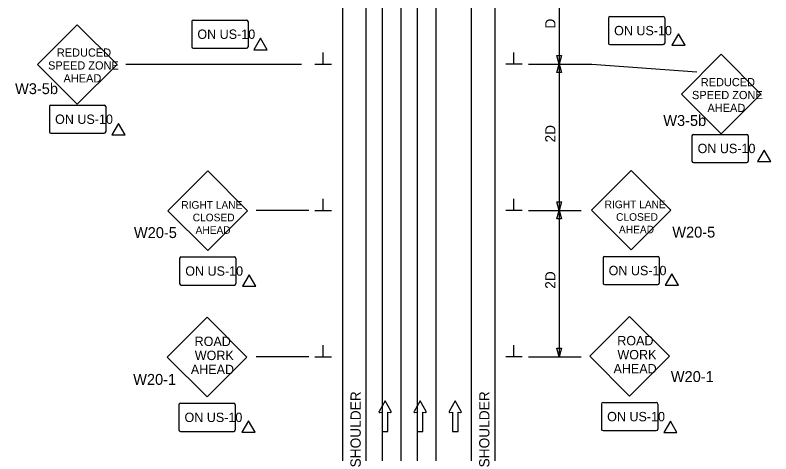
# Model space of a CAD drawing. Extents: x 16303 to 18475, y 5704 to 6974.
# Drawn here: x 16730 to 17246, y 6153 to 6453 of the extents above; entities that cross this region are included whole.
import ezdxf

# ---------------------------------------------------------------- set-up
doc = ezdxf.new("R2010")
doc.units = 0
for name, color, linetype in [('ALI_LEGAL_EX', 7, 'Continuous'), ('MT_SCRATCH_LEVEL_E', 7, 'Continuous'), ('PAVT_EDGE_EX', 7, 'Continuous'), ('TRAFFIC_SIGNS_PR', 7, 'Continuous'), ('TYPICAL_TEXT_DIMEN_PR', 7, 'Continuous')]:
    doc.layers.add(name, color=color, linetype=linetype)

msp = doc.modelspace()

# ---------------------------------------------------------------- linework, layer by layer
at = {"layer": 'ALI_LEGAL_EX'}
for p, q in [((16980.68, 6974.12), (16980.68, 6155.98)), ((17004.68, 6974.12), (17004.68, 6155.98)), ((16980.68, 6877.04), (16980.68, 6013.12)), ((17004.68, 6877.04), (17004.68, 6013.12)), ((16993.65, 6024.8), (16993.65, 6525.15)), ((17017.65, 6024.8), (17017.65, 6525.15))]:
    msp.add_line(p, q, dxfattribs=at)
for points in [[(16993.65, 6424.8), (16993.65, 6449.8)], [(17017.65, 6424.8), (17017.65, 6449.8)], [(16993.65, 6324.8), (16993.65, 6349.8)], [(17017.65, 6324.8), (17017.65, 6349.8)], [(16993.65, 6224.8), (16993.65, 6249.8)], [(17017.65, 6224.8), (17017.65, 6249.8)]]:
    msp.add_lwpolyline(points, dxfattribs=at)
at = {"layer": 'MT_SCRATCH_LEVEL_E'}
for p, q in [((16982.72, 6189.09), (16978.61, 6181.85)), ((16986.86, 6181.85), (16982.72, 6189.09)), ((17006.62, 6189.09), (17002.51, 6181.85)), ((17010.77, 6181.85), (17006.62, 6189.09)), ((17030.67, 6189.09), (17026.56, 6181.85)), ((17034.82, 6181.85), (17030.67, 6189.09)), ((16979.09, 6181.17), (16980.87, 6181.49)), ((16980.87, 6181.49), (16980.87, 6168.23)), ((16984.61, 6168.23), (16984.61, 6181.49)), ((16984.61, 6181.49), (16986.38, 6181.17)), ((17002.99, 6181.17), (17004.77, 6181.49)), ((17004.77, 6181.49), (17004.77, 6168.23)), ((17008.51, 6168.23), (17008.51, 6181.49)), ((17008.51, 6181.49), (17010.29, 6181.17)), ((17027.05, 6181.17), (17028.82, 6181.49)), ((17028.82, 6181.49), (17028.82, 6168.23)), ((17032.56, 6168.23), (17032.56, 6181.49)), ((17032.56, 6181.49), (17034.34, 6181.17)), ((16980.87, 6168.23), (16984.61, 6168.23)), ((17004.77, 6168.23), (17008.51, 6168.23)), ((17028.82, 6168.23), (17032.56, 6168.23))]:
    msp.add_line(p, q, dxfattribs=at)
for centre, start, end in [((16979.01, 6181.63), 150.4248, 279.9638), ((16986.45, 6181.63), 260.0362, 29.7731), ((17002.92, 6181.63), 150.4248, 279.9638), ((17010.36, 6181.63), 260.0362, 29.7731), ((17026.97, 6181.63), 150.4248, 279.9638), ((17034.41, 6181.63), 260.0362, 29.7731)]:
    msp.add_arc(centre, 0.463, start, end, dxfattribs=at)
at = {"layer": 'PAVT_EDGE_EX'}
for p, q in [((16953.65, 6525.15), (16953.65, 6062.71)), ((16969.65, 6525.15), (16969.65, 6062.71)), ((17041.65, 6525.15), (17041.65, 6062.71)), ((17057.65, 6525.15), (17057.65, 6062.71))]:
    msp.add_line(p, q, dxfattribs=at)
at = {"layer": 'TRAFFIC_SIGNS_PR'}
for p, q in [((17135.31, 6450.77), (17135.31, 6433.57)), ((17136.31, 6451.77), (17172.71, 6451.77)), ((17173.71, 6450.77), (17173.71, 6433.57)), ((16772.61, 6446.21), (16745.46, 6419.05)), ((16799.76, 6419.05), (16772.61, 6446.21)), ((16850.76, 6448.3), (16850.76, 6431.1)), ((16851.76, 6449.3), (16888.17, 6449.3)), ((16889.17, 6448.3), (16889.17, 6431.1)), ((16851.76, 6430.1), (16888.17, 6430.1)), ((17136.31, 6432.57), (17172.71, 6432.57)), ((17212.26, 6425.99), (17185.11, 6398.83)), ((17239.41, 6398.83), (17212.26, 6425.99)), ((16745.46, 6419.05), (16772.61, 6391.9)), ((16772.61, 6391.9), (16799.76, 6419.05)), ((17185.11, 6398.83), (17212.26, 6371.68)), ((17212.26, 6371.68), (17239.41, 6398.83)), ((16753.62, 6390.21), (16753.62, 6373.01)), ((16754.62, 6391.21), (16791.02, 6391.21)), ((16792.02, 6390.21), (16792.02, 6373.01)), ((16754.62, 6372.01), (16791.02, 6372.01)), ((17192.3, 6370.22), (17192.3, 6353.02)), ((17193.3, 6371.22), (17229.7, 6371.22)), ((17230.7, 6370.22), (17230.7, 6353.02)), ((17193.3, 6352.02), (17229.7, 6352.02)), ((16861.7, 6346.22), (16834.54, 6319.06)), ((16888.86, 6319.06), (16861.7, 6346.22)), ((17150.76, 6346.55), (17123.6, 6319.39)), ((17177.92, 6319.39), (17150.76, 6346.55)), ((16834.54, 6319.06), (16861.7, 6291.9)), ((16861.7, 6291.9), (16888.86, 6319.06)), ((17123.6, 6319.39), (17150.76, 6292.24)), ((17150.76, 6292.24), (17177.92, 6319.39)), ((16842.5, 6286.46), (16842.5, 6269.26)), ((16843.5, 6287.46), (16879.9, 6287.46)), ((16880.9, 6286.46), (16880.9, 6269.26)), ((17131.56, 6286.79), (17131.56, 6269.59)), ((17132.56, 6287.79), (17168.96, 6287.79)), ((17169.96, 6286.79), (17169.96, 6269.59)), ((16843.5, 6268.26), (16879.9, 6268.26)), ((17132.56, 6268.59), (17168.96, 6268.59)), ((16861.19, 6246.23), (16834.04, 6219.07)), ((16888.35, 6219.07), (16861.19, 6246.23)), ((17149.75, 6246.73), (17122.59, 6219.58)), ((17176.9, 6219.58), (17149.75, 6246.73)), ((16834.04, 6219.07), (16861.19, 6191.91)), ((16861.19, 6191.91), (16888.35, 6219.07)), ((17122.59, 6219.58), (17149.75, 6192.42)), ((17149.75, 6192.42), (17176.9, 6219.58)), ((16842.99, 6187.47), (16879.4, 6187.47)), ((17130.55, 6186.98), (17130.55, 6169.77)), ((17131.55, 6187.98), (17167.95, 6187.98)), ((17168.95, 6186.98), (17168.95, 6169.77)), ((16841.99, 6186.47), (16841.99, 6169.27)), ((16880.4, 6186.47), (16880.4, 6169.27)), ((16842.99, 6168.27), (16879.4, 6168.27)), ((17131.55, 6168.77), (17167.95, 6168.77))]:
    msp.add_line(p, q, dxfattribs=at)
for centre, start, end in [((17136.31, 6450.77), 90, 180), ((17172.71, 6450.77), 0, 90), ((16851.76, 6448.3), 90, 180), ((16888.17, 6448.3), 0, 90), ((16851.76, 6431.1), 180, 270), ((16888.17, 6431.1), 270, 0), ((17136.31, 6433.57), 180, 270), ((17172.71, 6433.57), 270, 0), ((16754.62, 6390.21), 90, 180), ((16791.02, 6390.21), 0, 90), ((16754.62, 6373.01), 180, 270), ((16791.02, 6373.01), 270, 0), ((17193.3, 6370.22), 90, 180), ((17229.7, 6370.22), 0, 90), ((17193.3, 6353.02), 180, 270), ((17229.7, 6353.02), 270, 0), ((16843.5, 6286.46), 90, 180), ((16879.9, 6286.46), 0, 90), ((17132.56, 6286.79), 90, 180), ((17168.96, 6286.79), 0, 90), ((17132.56, 6269.59), 180, 270), ((17168.96, 6269.59), 270, 0), ((16843.5, 6269.26), 180, 270), ((16879.9, 6269.26), 270, 0), ((16842.99, 6186.47), 90, 180), ((16879.4, 6186.47), 0, 90), ((17131.55, 6186.98), 90, 180), ((17167.95, 6186.98), 0, 90), ((16842.99, 6169.27), 180, 270), ((16879.4, 6169.27), 270, 0), ((17131.55, 6169.77), 180, 270), ((17167.95, 6169.77), 270, 0)]:
    msp.add_arc(centre, 1, start, end, dxfattribs=at)
at = {"layer": 'TYPICAL_TEXT_DIMEN_PR'}
for p, q in [((17101.65, 6469.33), (17101.65, 6419.33)), ((16940.52, 6419.33), (16940.52, 6427.11)), ((17070.77, 6419.33), (17070.77, 6427.11)), ((17101.65, 6419.33), (17100.08, 6425.19)), ((17100.08, 6425.19), (17101.65, 6425.19)), ((17101.65, 6425.19), (17103.22, 6425.19)), ((17103.22, 6425.19), (17101.65, 6419.33)), ((16805.82, 6419.33), (16925.67, 6419.33)), ((16934.9, 6419.33), (16946.15, 6419.33)), ((17076.4, 6419.33), (17065.15, 6419.33)), ((17080.65, 6419.33), (17124.03, 6419.33)), ((17100.08, 6413.47), (17101.65, 6419.33)), ((17101.65, 6419.33), (17101.65, 6319.33)), ((17101.65, 6419.33), (17103.22, 6413.47)), ((17124.03, 6419.33), (17195.64, 6413.88)), ((17101.65, 6413.47), (17100.08, 6413.47)), ((17103.22, 6413.47), (17101.65, 6413.47)), ((16940.52, 6319.33), (16940.52, 6327.11)), ((17070.77, 6319.33), (17070.77, 6327.11)), ((17101.65, 6319.33), (17100.08, 6325.19)), ((17100.08, 6325.19), (17101.65, 6325.19)), ((17101.65, 6325.19), (17103.22, 6325.19)), ((17103.22, 6325.19), (17101.65, 6319.33)), ((16930.65, 6319.33), (16894.65, 6319.33)), ((16934.9, 6319.33), (16946.15, 6319.33)), ((17076.4, 6319.33), (17065.15, 6319.33)), ((17080.65, 6319.33), (17116.65, 6319.33)), ((17100.08, 6313.47), (17101.65, 6319.33)), ((17101.65, 6319.33), (17101.65, 6219.33)), ((17101.65, 6319.33), (17103.22, 6313.47)), ((17101.65, 6313.47), (17100.08, 6313.47)), ((17103.22, 6313.47), (17101.65, 6313.47)), ((16940.52, 6219.33), (16940.52, 6227.11)), ((17070.77, 6219.33), (17070.77, 6227.11)), ((17101.65, 6219.33), (17100.08, 6225.19)), ((17100.08, 6225.19), (17101.65, 6225.19)), ((17101.65, 6225.19), (17103.22, 6225.19)), ((17103.22, 6225.19), (17101.65, 6219.33)), ((16930.65, 6219.33), (16894.65, 6219.33)), ((16934.9, 6219.33), (16946.15, 6219.33)), ((17076.4, 6219.33), (17065.15, 6219.33)), ((17080.65, 6219.33), (17116.65, 6219.33))]:
    msp.add_line(p, q, dxfattribs=at)
for points in [[(17183.01, 6439.95), (17178.48, 6432.11), (17187.54, 6432.11)], [(16897.66, 6436.89), (16893.13, 6429.06), (16902.18, 6429.06)], [(16800.83, 6378.79), (16796.31, 6370.96), (16805.36, 6370.96)], [(17241.64, 6360.51), (17237.12, 6352.67), (17246.17, 6352.67)], [(16889.95, 6275.35), (16885.43, 6267.52), (16894.48, 6267.52)], [(17178.56, 6276.05), (17174.03, 6268.22), (17183.08, 6268.22)], [(16889.45, 6175.47), (16884.92, 6167.64), (16893.97, 6167.64)], [(17177.55, 6175.28), (17173.02, 6167.44), (17182.07, 6167.44)]]:
    msp.add_lwpolyline(points, close=True, dxfattribs=at)

# ---------------------------------------------------------------- texts
at = {"layer": 'TRAFFIC_SIGNS_PR'}
for s, height, p in [('ON US-10', 6.401, (17139.14, 6438.97)), ('ON US-10', 6.401, (16854.6, 6436.5)), ('REDUCED', 5.6, (16758.67, 6424.36)), ('SPEED ZONE', 5.6, (16752.66, 6415.56)), ('AHEAD', 5.6, (16763.22, 6406.76)), ('REDUCED', 5.6, (17198.32, 6404.14)), ('W3-5b', 7.44, (16730.12, 6398.75)), ('SPEED ZONE', 5.6, (17192.31, 6395.34)), ('AHEAD', 5.6, (17202.87, 6386.54)), ('ON US-10', 6.4, (16757.46, 6378.41)), ('W3-5b', 7.44, (17172.71, 6377.01)), ('ON US-10', 6.4, (17196.14, 6358.42)), ('RIGHT LANE', 5.201, (16843.62, 6320.45)), ('RIGHT LANE', 5.201, (17132.68, 6320.79)), ('CLOSED', 5.201, (16851.41, 6311.85)), ('CLOSED', 5.201, (17140.47, 6312.19)), ('W20-5', 7.441, (16811.29, 6300.4)), ('AHEAD', 5.201, (16853.36, 6303.25)), ('AHEAD', 5.201, (17142.42, 6303.59)), ('W20-5', 7.441, (17178.86, 6300.73)), ('ON US-10', 6.401, (16846.33, 6274.66)), ('ON US-10', 6.401, (17135.39, 6274.99)), ('ROAD', 6.401, (17141.29, 6227.11)), ('ROAD', 6.401, (16852.73, 6226.61)), ('WORK', 6.401, (16852.84, 6217.01)), ('WORK', 6.401, (17141.4, 6217.51)), ('AHEAD', 6.401, (16850.15, 6207.4)), ('AHEAD', 6.401, (17138.71, 6207.91)), ('W20-1', 7.441, (16810.78, 6200.08)), ('W20-1', 7.441, (17177.85, 6202.01)), ('ON US-10', 6.401, (16845.83, 6174.67)), ('ON US-10', 6.401, (17134.38, 6175.18))]:
    msp.add_text(s, height=height, dxfattribs=at).set_placement(p)
at = {"layer": 'TYPICAL_TEXT_DIMEN_PR'}
for s, p in [('D', (17099.09, 6443.55)), ('2D', (17099.09, 6365.69)), ('2D', (17099.09, 6265.69)), ('SHOULDER', (16966.14, 6143.64)), ('SHOULDER', (17054, 6143.64))]:
    msp.add_text(s, height=7, rotation=90, dxfattribs=at).set_placement(p)

doc.saveas('drawing.dxf')
